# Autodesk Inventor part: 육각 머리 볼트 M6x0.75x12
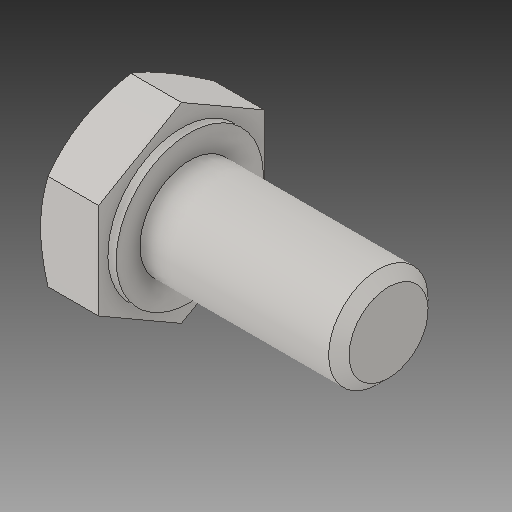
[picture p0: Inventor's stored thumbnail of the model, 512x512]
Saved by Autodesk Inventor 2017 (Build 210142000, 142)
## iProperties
Created: 2024-09
Part Number: 육각 머리 볼트 M6x0.75x12
Material: 일반
Description: 6각 머리 볼트 및 6각 머리 나사
Document SubType Name: Modeling
Designer: MRC
Density: 1 g/cm^3
Appearance: 기본값
Author: jhkim
Sending System: Autodesk Inventor 2025
Preprocessor: ST-DEVELOPER v20
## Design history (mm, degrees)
feature "Solid1"
node "솔리드1"
